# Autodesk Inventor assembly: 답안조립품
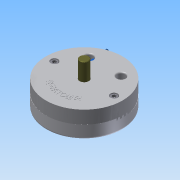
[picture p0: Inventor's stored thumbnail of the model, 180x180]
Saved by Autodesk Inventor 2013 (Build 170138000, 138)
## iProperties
Created: 2015-06
Part Number: 답안조립품
Document SubType Name: Assembly
Designer: Administrator
Author: Administrator
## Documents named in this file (10)
- C:\Documents and Settings\Administrator\바탕 화면\450631V1010\답안조립품.iam
- C:\Documents and Settings\Administrator\바탕 화면\450631V1010\1-본체.ipt
- C:\Documents and Settings\Administrator\바탕 화면\450631V1010\축.ipt
- C:\Documents and Settings\Administrator\바탕 화면\450631V1010\멈춤링.ipt
- C:\Documents and Settings\Administrator\바탕 화면\450631V1010\덮개.ipt
- C:\Documents and Settings\Administrator\바탕 화면\450631V1010\베어링62_22.ipt
- C:\Documents and Settings\Administrator\바탕 화면\450631V1010\평행핀.ipt
- C:\Documents and Settings\Administrator\바탕 화면\450631V1010\슬라이더2.ipt
- C:\Documents and Settings\Administrator\바탕 화면\450631V1010\슬라이더.ipt
- C:\Documents and Settings\Administrator\바탕 화면\450631V1010\M10x35.ipt
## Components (8 placed, 5 different names)
1. 1-본체:1
2. KS B 1336 22 x 1.2:1
3. KS B 1336 22 x 1.2:2
4. KS B 2023 62/22 - 22 x 50 x 14:1
5. KS B 2023 62/22 - 22 x 50 x 14:2
6. KS B 1320 B B 5 x  20:1
7. KS B 1003 - 미터 M 10 x 35:1
8. KS B 1003 - 미터 M 10 x 35:2
